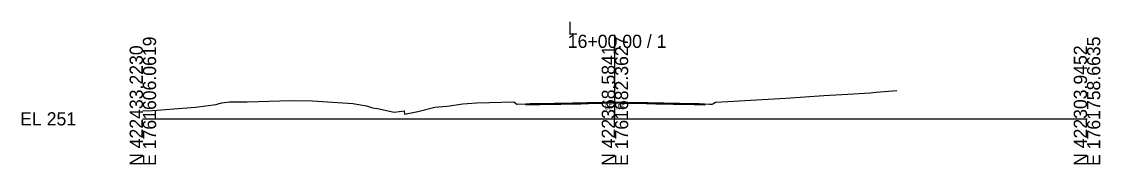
# Model space of a CAD drawing. Extents: x -26 to 3203, y -11010 to 4024.
# Drawn here: x -25.7 to 202.8, y -10509.7 to -10479.3 of the extents above; entities that cross this region are included whole.
import ezdxf

# ---------------------------------------------------------------- set-up
doc = ezdxf.new("R2010")
doc.units = 0
for name, color, linetype in [('Default', 7, 'Continuous'), ('Exist Cross Section Cell', 7, 'Continuous'), ('Exist XS Center Line Elevation Label', 7, 'Continuous'), ('Exist XS Ground Line', 7, 'Continuous'), ('Prop CMT Pvmt Course 1', 7, 'Continuous'), ('Scratch_Level_0', 7, 'Continuous')]:
    doc.layers.add(name, color=color, linetype=linetype)

msp = doc.modelspace()

# ---------------------------------------------------------------- linework, layer by layer
at = {"layer": 'Exist Cross Section Cell'}
for p, q in [((100, -10500), (100, -10482.13)), ((0, -10500), (100, -10500)), ((100, -10500), (200, -10500))]:
    msp.add_line(p, q, dxfattribs=at)
at = {"layer": 'Exist XS Ground Line'}
msp.add_lwpolyline([(0, -10498.23), (1.15, -10498.27), (11.13, -10497.54), (15.53, -10496.98), (16.17, -10496.73), (16.51, -10496.7), (16.69, -10496.58), (18.35, -10496.37), (18.87, -10496.4), (22.09, -10496.39), (31.37, -10496.1), (35.93, -10496.16), (44.48, -10496.73), (47.39, -10497.26), (48.62, -10497.68), (49.71, -10497.77), (53.21, -10498.56), (55.34, -10498.32), (55.44, -10499.04), (58.22, -10498.43), (61.84, -10497.53), (64.37, -10497.31), (64.93, -10497.23), (67.75, -10496.81), (70.69, -10496.62), (73.45, -10496.51), (78.59, -10496.38), (79.25, -10496.86), (79.27, -10496.88), (79.31, -10496.88), (81.11, -10496.79), (81.69, -10496.78), (82.06, -10496.77), (83.38, -10496.75), (83.76, -10496.74), (84.09, -10496.74), (85.54, -10496.72), (87.23, -10496.69), (87.45, -10496.68), (88.55, -10496.67), (90.65, -10496.64), (91.08, -10496.63), (92.78, -10496.6), (92.79, -10496.6), (94.03, -10496.54), (94.39, -10496.53), (94.95, -10496.52), (97.2, -10496.47), (98.81, -10496.45), (100.07, -10496.45), (100.42, -10496.45), (101.08, -10496.47), (102.67, -10496.49), (103.84, -10496.51), (106.58, -10496.53), (106.84, -10496.53), (107.07, -10496.54), (108.68, -10496.6), (110.26, -10496.63), (110.5, -10496.64), (112.39, -10496.68), (112.5, -10496.68), (113.69, -10496.7), (114.27, -10496.71), (116.81, -10496.76), (117.83, -10496.77), (118.57, -10496.79), (118.74, -10496.8), (118.94, -10496.82), (120.04, -10496.86), (120.61, -10496.88), (120.76, -10496.79), (121.32, -10496.45), (123.93, -10496.31), (128.75, -10496.01), (136.22, -10495.6), (144.22, -10495.07), (149.33, -10494.74), (154.08, -10494.47), (155.35, -10494.35), (159.74, -10494.01)], dxfattribs=at)
msp.add_lwpolyline([(0, -10498.23), (1.15, -10498.27), (11.13, -10497.54), (15.53, -10496.98), (16.17, -10496.73), (16.51, -10496.7), (16.69, -10496.58), (18.35, -10496.37), (18.87, -10496.4), (22.09, -10496.39), (31.37, -10496.1), (35.93, -10496.16), (44.48, -10496.73), (47.39, -10497.26), (48.62, -10497.68), (49.71, -10497.77), (53.21, -10498.56), (55.34, -10498.32), (55.44, -10499.04), (58.22, -10498.43), (61.84, -10497.53), (64.37, -10497.31), (64.93, -10497.23), (67.75, -10496.81), (70.69, -10496.62), (73.45, -10496.51), (78.59, -10496.38), (79.25, -10496.86), (79.27, -10496.88), (79.31, -10496.88), (81.11, -10496.79), (81.69, -10496.78), (82.06, -10496.77), (83.38, -10496.75), (83.76, -10496.74), (84.09, -10496.74), (85.54, -10496.72), (87.23, -10496.69), (87.45, -10496.68), (88.55, -10496.67), (90.65, -10496.64), (91.08, -10496.63), (92.78, -10496.6), (92.79, -10496.6), (94.03, -10496.54), (94.39, -10496.53), (94.95, -10496.52), (97.2, -10496.47), (98.81, -10496.45), (100.07, -10496.45), (100.42, -10496.45), (101.08, -10496.47), (102.67, -10496.49), (103.84, -10496.51), (106.58, -10496.53), (106.84, -10496.53), (107.07, -10496.54), (108.68, -10496.6), (110.26, -10496.63), (110.5, -10496.64), (112.39, -10496.68), (112.5, -10496.68), (113.69, -10496.7), (114.27, -10496.71), (116.81, -10496.76), (117.83, -10496.77), (118.57, -10496.79), (118.74, -10496.8), (118.94, -10496.82), (120.04, -10496.86), (120.61, -10496.88), (120.76, -10496.79), (121.32, -10496.45), (123.93, -10496.31), (128.75, -10496.01), (136.22, -10495.6), (144.22, -10495.07), (149.33, -10494.74), (154.08, -10494.47), (155.35, -10494.35), (159.74, -10494.01)], dxfattribs=at)
msp.add_lwpolyline([(0, -10498.23), (1.15, -10498.27), (11.13, -10497.54), (15.53, -10496.98), (16.17, -10496.73), (16.51, -10496.7), (16.69, -10496.58), (18.35, -10496.37), (18.87, -10496.4), (22.09, -10496.39), (31.37, -10496.1), (35.93, -10496.16), (44.48, -10496.73), (47.39, -10497.26), (48.62, -10497.68), (49.71, -10497.77), (53.21, -10498.56), (55.34, -10498.32), (55.44, -10499.04), (58.22, -10498.43), (61.84, -10497.53), (64.37, -10497.31), (64.93, -10497.23), (67.75, -10496.81), (70.69, -10496.62), (73.45, -10496.51), (78.59, -10496.38), (79.25, -10496.86), (79.27, -10496.88), (79.31, -10496.88), (81.11, -10496.79), (81.69, -10496.78), (82.06, -10496.77), (83.38, -10496.75), (83.76, -10496.74), (84.09, -10496.74), (85.54, -10496.72), (87.23, -10496.69), (87.45, -10496.68), (88.55, -10496.67), (90.65, -10496.64), (91.08, -10496.63), (92.78, -10496.6), (92.79, -10496.6), (94.03, -10496.54), (94.39, -10496.53), (94.95, -10496.52), (97.2, -10496.47), (98.81, -10496.45), (100.07, -10496.45), (100.42, -10496.45), (101.08, -10496.47), (102.67, -10496.49), (103.84, -10496.51), (106.58, -10496.53), (106.84, -10496.53), (107.07, -10496.54), (108.68, -10496.6), (110.26, -10496.63), (110.5, -10496.64), (112.39, -10496.68), (112.5, -10496.68), (113.69, -10496.7), (114.27, -10496.71), (116.81, -10496.76), (117.83, -10496.77), (118.57, -10496.79), (118.74, -10496.8), (118.94, -10496.82), (120.04, -10496.86), (120.61, -10496.88), (120.76, -10496.79), (121.32, -10496.45), (123.93, -10496.31), (128.75, -10496.01), (136.22, -10495.6), (144.22, -10495.07), (149.33, -10494.74), (154.08, -10494.47), (155.35, -10494.35), (159.74, -10494.01)], dxfattribs=at)
msp.add_lwpolyline([(0, -10498.23), (1.15, -10498.27), (11.13, -10497.54), (15.53, -10496.98), (16.17, -10496.73), (16.51, -10496.7), (16.69, -10496.58), (18.35, -10496.37), (18.87, -10496.4), (22.09, -10496.39), (31.37, -10496.1), (35.93, -10496.16), (44.48, -10496.73), (47.39, -10497.26), (48.62, -10497.68), (49.71, -10497.77), (53.21, -10498.56), (55.34, -10498.32), (55.44, -10499.04), (58.22, -10498.43), (61.84, -10497.53), (64.37, -10497.31), (64.93, -10497.23), (67.75, -10496.81), (70.69, -10496.62), (73.45, -10496.51), (78.59, -10496.38), (79.25, -10496.86), (79.27, -10496.88), (79.31, -10496.88), (81.11, -10496.79), (81.69, -10496.78), (82.06, -10496.77), (83.38, -10496.75), (83.76, -10496.74), (84.09, -10496.74), (85.54, -10496.72), (87.23, -10496.69), (87.45, -10496.68), (88.55, -10496.67), (90.65, -10496.64), (91.08, -10496.63), (92.78, -10496.6), (92.79, -10496.6), (94.03, -10496.54), (94.39, -10496.53), (94.95, -10496.52), (97.2, -10496.47), (98.81, -10496.45), (100.07, -10496.45), (100.42, -10496.45), (101.08, -10496.47), (102.67, -10496.49), (103.84, -10496.51), (106.58, -10496.53), (106.84, -10496.53), (107.07, -10496.54), (108.68, -10496.6), (110.26, -10496.63), (110.5, -10496.64), (112.39, -10496.68), (112.5, -10496.68), (113.69, -10496.7), (114.27, -10496.71), (116.81, -10496.76), (117.83, -10496.77), (118.57, -10496.79), (118.74, -10496.8), (118.94, -10496.82), (120.04, -10496.86), (120.61, -10496.88), (120.76, -10496.79), (121.32, -10496.45), (123.93, -10496.31), (128.75, -10496.01), (136.22, -10495.6), (144.22, -10495.07), (149.33, -10494.74), (154.08, -10494.47), (155.35, -10494.35), (159.74, -10494.01)], dxfattribs=at)
msp.add_lwpolyline([(0, -10498.23), (1.15, -10498.27), (11.13, -10497.54), (15.53, -10496.98), (16.17, -10496.73), (16.51, -10496.7), (16.69, -10496.58), (18.35, -10496.37), (18.87, -10496.4), (22.09, -10496.39), (31.37, -10496.1), (35.93, -10496.16), (44.48, -10496.73), (47.39, -10497.26), (48.62, -10497.68), (49.71, -10497.77), (53.21, -10498.56), (55.34, -10498.32), (55.44, -10499.04), (58.22, -10498.43), (61.84, -10497.53), (64.37, -10497.31), (64.93, -10497.23), (67.75, -10496.81), (70.69, -10496.62), (73.45, -10496.51), (78.59, -10496.38), (79.25, -10496.86), (79.27, -10496.88), (79.31, -10496.88), (81.11, -10496.79), (81.69, -10496.78), (82.06, -10496.77), (83.38, -10496.75), (83.76, -10496.74), (84.09, -10496.74), (85.54, -10496.72), (87.23, -10496.69), (87.45, -10496.68), (88.55, -10496.67), (90.65, -10496.64), (91.08, -10496.63), (92.78, -10496.6), (92.79, -10496.6), (94.03, -10496.54), (94.39, -10496.53), (94.95, -10496.52), (97.2, -10496.47), (98.81, -10496.45), (100.07, -10496.45), (100.42, -10496.45), (101.08, -10496.47), (102.67, -10496.49), (103.84, -10496.51), (106.58, -10496.53), (106.84, -10496.53), (107.07, -10496.54), (108.68, -10496.6), (110.26, -10496.63), (110.5, -10496.64), (112.39, -10496.68), (112.5, -10496.68), (113.69, -10496.7), (114.27, -10496.71), (116.81, -10496.76), (117.83, -10496.77), (118.57, -10496.79), (118.74, -10496.8), (118.94, -10496.82), (120.04, -10496.86), (120.61, -10496.88), (120.76, -10496.79), (121.32, -10496.45), (123.93, -10496.31), (128.75, -10496.01), (136.22, -10495.6), (144.22, -10495.07), (149.33, -10494.74), (154.08, -10494.47), (155.35, -10494.35), (159.74, -10494.01)], dxfattribs=at)
at = {"layer": 'Prop CMT Pvmt Course 1'}
for points in [[(81.1, -10496.79), (81.11, -10496.79), (81.69, -10496.78), (82.06, -10496.77), (83.38, -10496.75), (83.76, -10496.74), (84.09, -10496.74), (85.54, -10496.72), (87.23, -10496.69), (87.45, -10496.68), (88.55, -10496.67), (90.65, -10496.64), (91.08, -10496.63), (92.78, -10496.6), (92.79, -10496.6), (94.03, -10496.54), (94.39, -10496.53), (94.95, -10496.52), (97.2, -10496.47), (98.81, -10496.45), (100, -10496.45)], [(100, -10496.45), (100, -10496.7)], [(100, -10496.45), (100.07, -10496.45), (100.42, -10496.45), (101.08, -10496.47), (102.67, -10496.49), (103.84, -10496.51), (106.58, -10496.53), (106.84, -10496.53), (107.07, -10496.54), (108.68, -10496.6), (110.26, -10496.63), (110.5, -10496.64), (112.39, -10496.68), (112.5, -10496.68), (113.69, -10496.7), (114.27, -10496.71), (116.81, -10496.76), (117.83, -10496.77), (118.57, -10496.79), (118.74, -10496.8), (118.94, -10496.82), (118.94, -10496.82)], [(100, -10496.7), (100, -10496.45)], [(100, -10496.7), (98.81, -10496.7), (97.2, -10496.72), (94.95, -10496.77), (94.39, -10496.78), (94.03, -10496.79), (92.79, -10496.85), (92.78, -10496.85), (91.08, -10496.88), (90.65, -10496.89), (88.55, -10496.92), (87.45, -10496.93), (87.23, -10496.94), (85.54, -10496.97), (84.09, -10496.99), (83.76, -10496.99), (83.38, -10497), (82.06, -10497.02), (81.69, -10497.03), (81.11, -10497.04), (81.1, -10497.04)], [(81.1, -10497.04), (81.1, -10496.79)], [(118.94, -10497.07), (118.94, -10497.07), (118.74, -10497.05), (118.57, -10497.04), (117.83, -10497.02), (116.81, -10497.01), (114.27, -10496.96), (113.69, -10496.95), (112.5, -10496.93), (112.39, -10496.93), (110.5, -10496.89), (110.26, -10496.88), (108.68, -10496.85), (107.07, -10496.79), (106.84, -10496.78), (106.58, -10496.78), (103.84, -10496.76), (102.67, -10496.74), (101.08, -10496.72), (100.42, -10496.7), (100.07, -10496.7), (100, -10496.7)], [(118.94, -10496.82), (118.94, -10497.07)]]:
    msp.add_lwpolyline(points, dxfattribs=at)

# ---------------------------------------------------------------- texts
at = {"layer": 'Default'}
msp.add_text('-', height=0.0001, dxfattribs=at).set_placement((0, -10500))
at = {"layer": 'Exist Cross Section Cell'}
for s, p in [('L', (90, -10482.13)), ('16+00.00 / 1', (90, -10484.93)), ('EL 251', (-26, -10501.4))]:
    msp.add_text(s, height=2.8, dxfattribs=at).set_placement(p)
for s, p in [('E 1761606.0619', (2.8, -10510)), ('E 1761682.3627', (102.8, -10510)), ('E 1761758.6635', (202.8, -10510)), ('N 422433.2230', (0, -10510)), ('N 422368.5841', (100, -10510)), ('N 422303.9452', (200, -10510))]:
    msp.add_text(s, height=2.8, rotation=90, dxfattribs=at).set_placement(p)
at = {"layer": 'Exist XS Center Line Elevation Label'}
msp.add_text('254.55', height=1, dxfattribs=at).set_placement((97.87, -10497.95))
at = {"layer": 'Scratch_Level_0'}
for s, p in [('PV1_PGL', (99.95, -10496.46)), ('Exterior Boundary', (80.94, -10496.8)), ('LT_Res Edge', (80.99, -10496.8)), ('Exterior Boundary', (118.79, -10496.83)), ('RT_Res_Edge', (118.84, -10496.83))]:
    msp.add_text(s, height=0.02, dxfattribs=at).set_placement(p)

doc.saveas('drawing.dxf')
